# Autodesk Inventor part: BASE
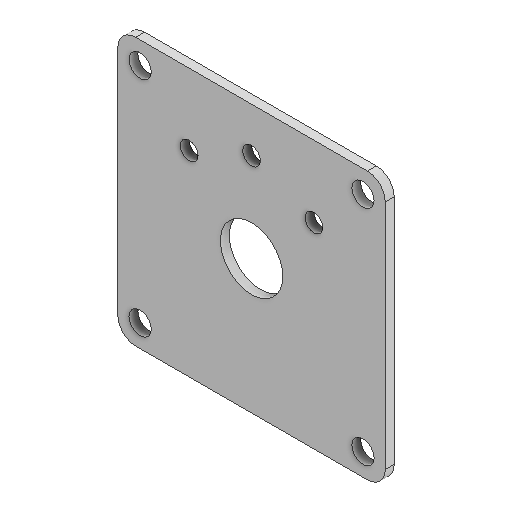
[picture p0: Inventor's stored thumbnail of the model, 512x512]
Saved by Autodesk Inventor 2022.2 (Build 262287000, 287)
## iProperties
Created: 2025-01
Part Number: BASE
Material: Generico
Document SubType Name: Modeling
Designer: 18907419
Density: 1 g/cm^3
Appearance: Default
Author: 18907419
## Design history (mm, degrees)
node "Solido1"
feature "BASE"
